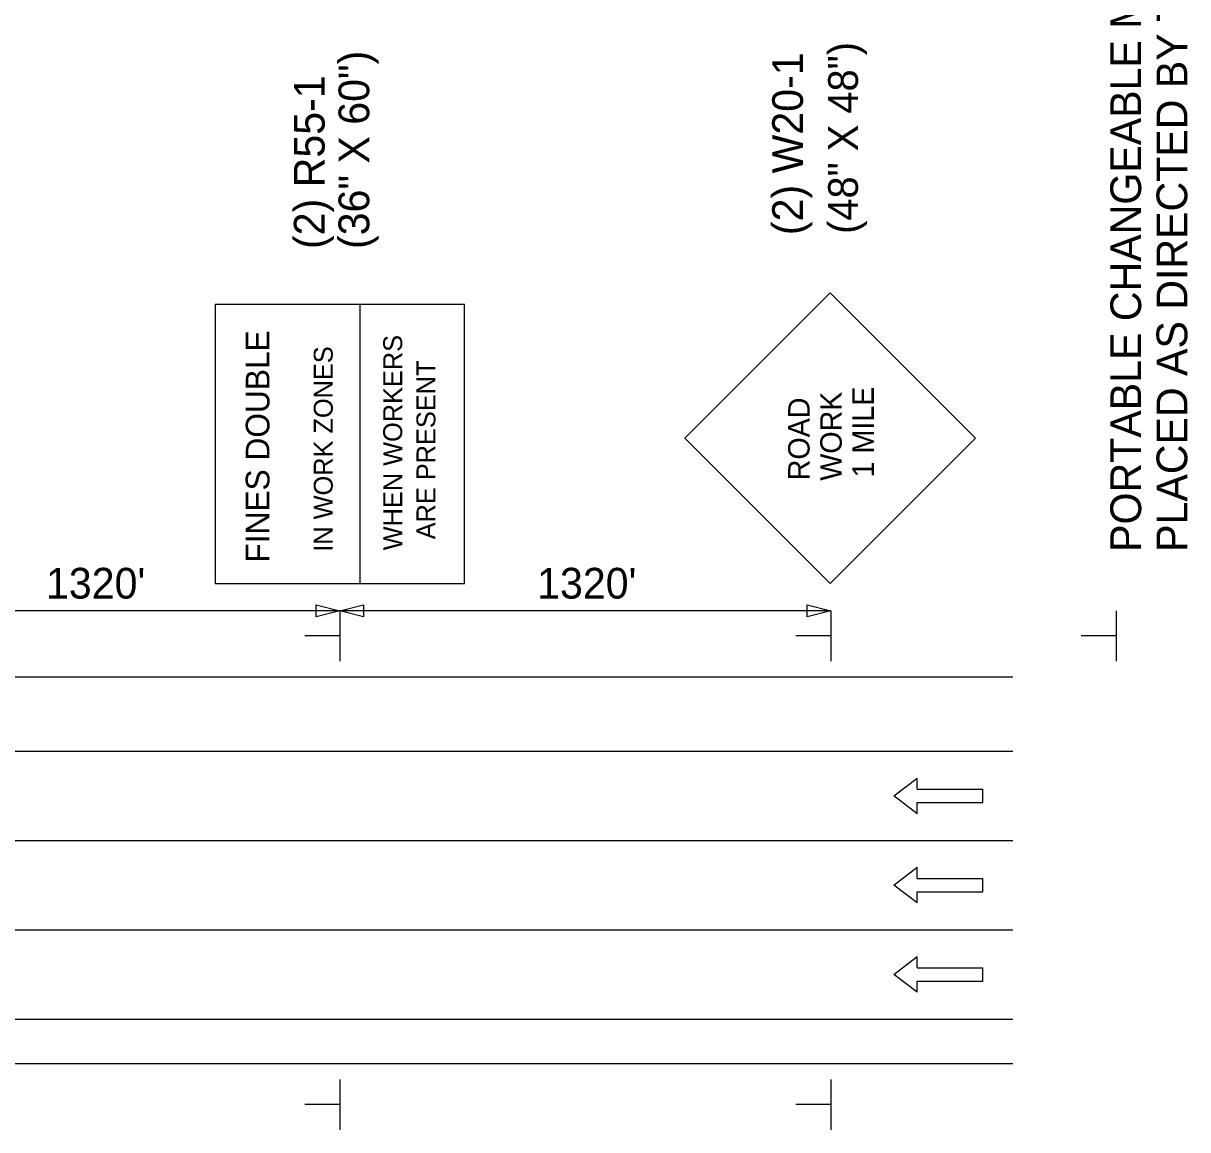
# Model space of a CAD drawing. Extents: x 1017892 to 1236694, y 658553 to 792468.
# Drawn here: x 1023877 to 1024463, y 659722 to 660280 of the extents above; entities that cross this region are included whole.
import ezdxf

# ---------------------------------------------------------------- set-up
doc = ezdxf.new("R2010")
doc.units = 0
for name, color, linetype in [('Level 1', 7, 'Continuous'), ('Level 3', 7, 'Continuous'), ('Level 8', 7, 'Continuous'), ('R_Const Phase All', 7, 'Continuous'), ('R_Proposed Road Annot', 7, 'Continuous')]:
    doc.layers.add(name, color=color, linetype=linetype)

msp = doc.modelspace()

# ---------------------------------------------------------------- linework, layer by layer
at = {"layer": 'Level 1'}
for p, q in [((1024046.15, 660137.78), (1024046.15, 659997.09)), ((1024315.26, 659890.09), (1024326.94, 659899.09)), ((1024326.94, 659893.46), (1024326.94, 659899.09)), ((1024326.94, 659881.09), (1024315.26, 659890.09)), ((1024326.94, 659893.46), (1024360.05, 659893.46)), ((1024360.05, 659886.71), (1024360.05, 659893.46)), ((1024326.94, 659886.71), (1024360.05, 659886.71)), ((1024326.94, 659881.09), (1024326.94, 659886.71)), ((1024315.26, 659845.09), (1024326.94, 659854.09)), ((1024326.94, 659848.46), (1024326.94, 659854.09)), ((1024326.94, 659848.46), (1024360.05, 659848.46)), ((1024360.05, 659841.71), (1024360.05, 659848.46)), ((1024326.94, 659836.09), (1024315.26, 659845.09)), ((1024326.94, 659841.71), (1024360.05, 659841.71)), ((1024326.94, 659836.09), (1024326.94, 659841.71)), ((1024315.26, 659800.09), (1024326.94, 659809.09)), ((1024326.94, 659803.46), (1024326.94, 659809.09)), ((1024326.94, 659803.46), (1024360.05, 659803.46)), ((1024360.05, 659796.71), (1024360.05, 659803.46)), ((1024326.94, 659791.09), (1024315.26, 659800.09)), ((1024326.94, 659796.71), (1024360.05, 659796.71)), ((1024326.94, 659791.09), (1024326.94, 659796.71))]:
    msp.add_line(p, q, dxfattribs=at)
at = {"layer": 'Level 3'}
for p, q in [((1024036.07, 659983.39), (1024036.07, 659958.08)), ((1024283.57, 659983.39), (1024283.57, 659958.08)), ((1024427.26, 659983.39), (1024427.26, 659958.08)), ((1024035.7, 659970.8), (1024018.43, 659970.8)), ((1024283.2, 659970.8), (1024265.93, 659970.8)), ((1024426.89, 659970.8), (1024409.62, 659970.8)), ((1024036.07, 659747.08), (1024036.07, 659721.77)), ((1024283.57, 659747.08), (1024283.57, 659721.77)), ((1024035.7, 659734.49), (1024018.43, 659734.49)), ((1024283.2, 659734.49), (1024265.93, 659734.49))]:
    msp.add_line(p, q, dxfattribs=at)
msp.add_lwpolyline([(1023973.2, 659997.09), (1024098.95, 659997.09), (1024098.95, 660137.78), (1023973.2, 660137.78)], close=True, dxfattribs=at)
at = {"layer": 'Level 8'}
for p, q in [((1024283.24, 660143.69), (1024209.94, 660070.38)), ((1024283.24, 660143.69), (1024356.48, 660070.39)), ((1024209.94, 660070.38), (1024283.24, 659997.09)), ((1024356.48, 660070.39), (1024283.24, 659997.09))]:
    msp.add_line(p, q, dxfattribs=at)
at = {"layer": 'R_Const Phase All'}
for p, q in [((1023214.87, 659950.09), (1024375.31, 659950.09)), ((1023214.87, 659912.59), (1024375.31, 659912.59)), ((1023214.87, 659867.59), (1024375.31, 659867.59)), ((1023214.87, 659822.59), (1024375.31, 659822.59)), ((1023214.87, 659777.59), (1024375.31, 659777.59)), ((1023214.87, 659755.09), (1024375.31, 659755.09))]:
    msp.add_line(p, q, dxfattribs=at)
at = {"layer": 'R_Proposed Road Annot'}
for points in [[(1024036.07, 659983.39), (1023788.57, 659983.39)], [(1024283.57, 659983.39), (1024036.07, 659983.39)]]:
    msp.add_lwpolyline(points, dxfattribs=at)
for points in [[(1024024.07, 659986.39), (1024036.07, 659983.39), (1024024.07, 659980.39)], [(1024048.07, 659980.39), (1024036.07, 659983.39), (1024048.07, 659986.39)], [(1024271.57, 659986.39), (1024283.57, 659983.39), (1024271.57, 659980.39)]]:
    msp.add_lwpolyline(points, close=True, dxfattribs=at)

# ---------------------------------------------------------------- texts
at = {"layer": 'Level 8'}
for s, height, rotation, p in [('(36" X 60")', 15.5, 90, (1024050.9, 660165.82)), ('(2) W20-1', 15.5, 90, (1024269.46, 660172.82)), ('(48" X 48")', 15, 90, (1024297.16, 660173.44)), ('(2) R55-1', 15.5, 90, (1024028.41, 660165.82)), ('FINES DOUBLE', 11.94, 90, (1024000.59, 660007.71)), ('WHEN WORKERS', 9.5524, 90, (1024067.49, 660013.91)), ('IN WORK ZONES', 9.5504, 90, (1024032.49, 660013.18)), ('ARE PRESENT', 9.5524, 90, (1024084.24, 660019.44)), ('WORK', 10.797, 90.00004, (1024289, 660049)), ('1 MILE', 10.799, 90.00057, (1024305.19, 660050.66)), ('ROAD', 10.799, 90.00045, (1024272.8, 660049.21))]:
    msp.add_text(s, height=height, rotation=rotation, dxfattribs=at).set_placement(p)
at = {"layer": 'R_Const Phase All'}
for s, p in [('PORTABLE CHANGEABLE MESSAGE SIGN ', (1024439.89, 660013.11)), ('PLACED AS DIRECTED BY THE ENGINEER.', (1024463.14, 660013.11))]:
    msp.add_text(s, height=15.5, rotation=90, dxfattribs=at).set_placement(p)
at = {"layer": 'R_Proposed Road Annot'}
for p in [(1023887.97, 659989.56), (1024135.47, 659989.56)]:
    msp.add_text("1320'", height=15.5, dxfattribs=at).set_placement(p)

doc.saveas('drawing.dxf')
